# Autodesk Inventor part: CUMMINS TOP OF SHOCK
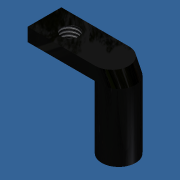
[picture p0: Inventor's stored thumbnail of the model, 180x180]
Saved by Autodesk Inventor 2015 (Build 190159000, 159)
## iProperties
Created: 2014-10
Part Number: CUMMINS TOP OF SHOCK
Material: Generic
Document SubType Name: Modeling
Designer: caovt
Density: 1 g/cm^3
Appearance: Default
Author: caovt
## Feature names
1. Extrusion1
2. Sweep1
3. Extrusion2
4. Extrusion3
5. Extrusion4
## Parameters: d0 = 25.4 mm, d1 = 19.05 mm, d4 = 12.7 mm, d5 = 0, d8 = 0, d9 = 0, d10 = 25.4 mm, d11 = 0, d12 = 9.525 mm, d13 = 15.875 mm, d14 = 0, d15 = 6.35 mm, d16 = 15.875 mm, d17 = 0, d18 = 25.4 mm, d19 = 0
